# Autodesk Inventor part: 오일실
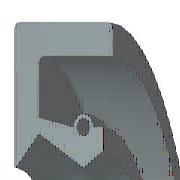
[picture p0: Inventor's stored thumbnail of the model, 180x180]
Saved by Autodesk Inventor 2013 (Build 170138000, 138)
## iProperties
IsCustomPart: 1
Created: 2009-02
Part Number: 오일실
Material: 고무
Description: 오일-실
Document SubType Name: Modeling
Standard: KS B 2804
Designer: SeoGD™[esajin.kr]
Standards Organization: KS
Language: ko-KR
Size Designation: D - 15 25 7
Categories: <MemberInstance><Categories><Category DisplayName="샤프트 부품" InternalName="7f7aeb1f-a693-4053-b835-cee3144e0d98" Mnemonic="SHFT"><Category DisplayName="실링" Intern
Density: 0.93 g/cm^3
Author: SeoGD™[esajin.kr]
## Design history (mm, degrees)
revolve "본체" stored, may be unused: angle "d17" = 90 deg
revolve "스프링1" stored, may be unused: angle "d18" = 90 deg
body "Solid1"
sketch "스케치1"
  geometry: L1 (0, 12.5)-(7, 12.5); L2 (7, 10.75)-(1.75, 10.75); L3 (1.75, 9.25)-(4.9, 7.5); L4 (4.9, 7.5)-(0, 7.5); L5 (0, 0)-(9.586, 0) reference; L6 (4.9, 7.5)-(6.3, 8.375); L7 (0, 18)-(0, -3) reference; L8 (-1.941, 0)-(11.507, 0) reference; L9 (4.2, 9.6)-(1.75, 10.09); L10 (1.75, 10.09)-(1.75, 10.75); L11 (0, 12.5)-(0, 7.588); L12 (4.9, 7.5)-(0, 7.5); L13 (1.75, 9.25)-(0.152, 7.528); L14 (7, 12.5)-(7, 10.75); L15 (5.6, 9.6)-(6.3, 9.6); L16 (6.3, 9.6)-(6.3, 8.375); C1 r 0.455 at (4.9, 9.6); A1 r 0.7 centre (4.9, 9.6) between (5.6, 9.6) and (4.2, 9.6); A2 r 0.088 centre (0.088, 7.588) between (0, 7.588) and (0.152, 7.528); 1 further point
  constraints: 28 end point, 5 horizontal alignment, 5 point on line, 4 point on circle, 4 vertical alignment, 3 centre point, 3 tangent, 2 collinear, 2 horizontal, 2 perpendicular, 1 coincident, 1 parallel
  dimensions: "d0" = 25 diameter of L1 L5 (= SD2); "d1" = 1.75 distance of L1.end L2.start (= SD); "d2" = 0.91 diameter of C1 (= SPDI); "d3" = 1.4 diameter of A1 (= SPDA); "d4" = 15 diameter of L3.end L5 (= NND); "d5" = 18.5 diameter of L3.start L5 (= TKDM); "d7" = 20.18 diameter of L9.end L5 (= TKDM + 0.24 x SWDT); "d8" = 1.75 distance between parallel lines of L11 L10 (= SD); "d9" = 4.9 distance from line of L11 C1.centre (= SPDST); "d10" = 19.2 diameter of C1.centre L5 (= HLDM); "d11" = 0.0875 radius of A2 (= 0.25 x LAB); "d12" = 6.3 distance between parallel lines of L11 L16 (= SDI); "d13" = 16.75 diameter of L6.end L5 (= ABDM); "d14" = 7 distance from line of L11 L1.end (= SWDT)
fillet "모깎기1" dims "d6" = 0.3 (= RR)
other parameters: "SD2" = 25 [user parameter; used in 1 equation term], "SWDT" = 7 [user parameter; used in 2 equation terms], "RR" = 0.3 [user parameter; used in 1 equation term], "SD" = 1.75 [user parameter; used in 2 equation terms], "NND" = 15 [user parameter; used in 1 equation term], "SPDA" = 1.4 [user parameter; used in 1 equation term], "SPDI" = 0.91 [user parameter; used in 1 equation term], "TKDM" = 18.5 [user parameter; used in 2 equation terms], "HLDM" = 19.2 [user parameter; used in 1 equation term], "ABDM" = 16.75 [user parameter; used in 1 equation term], "SDI" = 6.3 [user parameter; used in 1 equation term], "SPDST" = 4.9 [user parameter; used in 1 equation term], "LAB" = 0.35 [user parameter; used in 1 equation term], "d15" = 0, "d16" = 0, "d19" = 0
